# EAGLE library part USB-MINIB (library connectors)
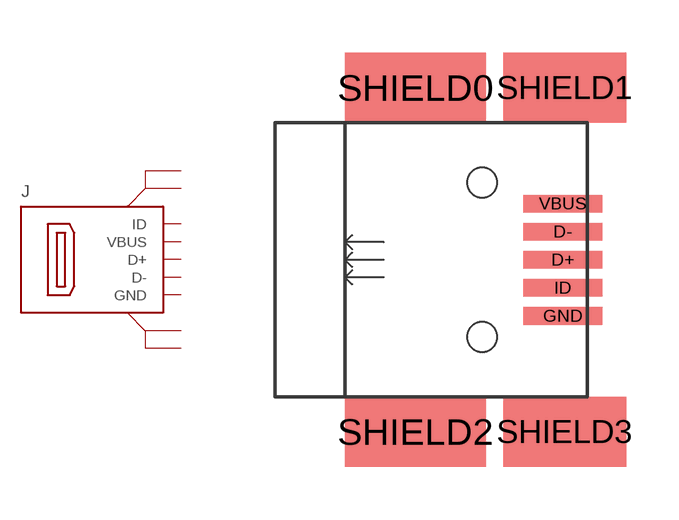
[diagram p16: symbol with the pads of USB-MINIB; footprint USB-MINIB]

Designator prefix J

## USB-MINIB  [USB-MINIB]
D+  D+
D-  D-
GND  GND  pwr
ID  ID
SHIELD0  SCREEN  pas
SHIELD1  SCREEN  pas
SHIELD2  SCREEN  pas
SHIELD3  SCREEN  pas
VBUS  VBUS  pwr

## Footprint USB-MINIB (pad centres in mm)
smd 2.25 x 0.5: D+ 0,0; D- 0,0.8; GND 0,-1.6; ID 0,-0.8; VBUS 0,1.6
smd 4 x 2: SHIELD0 -4.2,4.9; SHIELD2 -4.2,-4.9
smd 3.5 x 2: SHIELD1 0.05,4.9; SHIELD3 0.05,-4.9
hole 0.85 at -2.3,2.2
hole 0.85 at -2.3,-2.2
